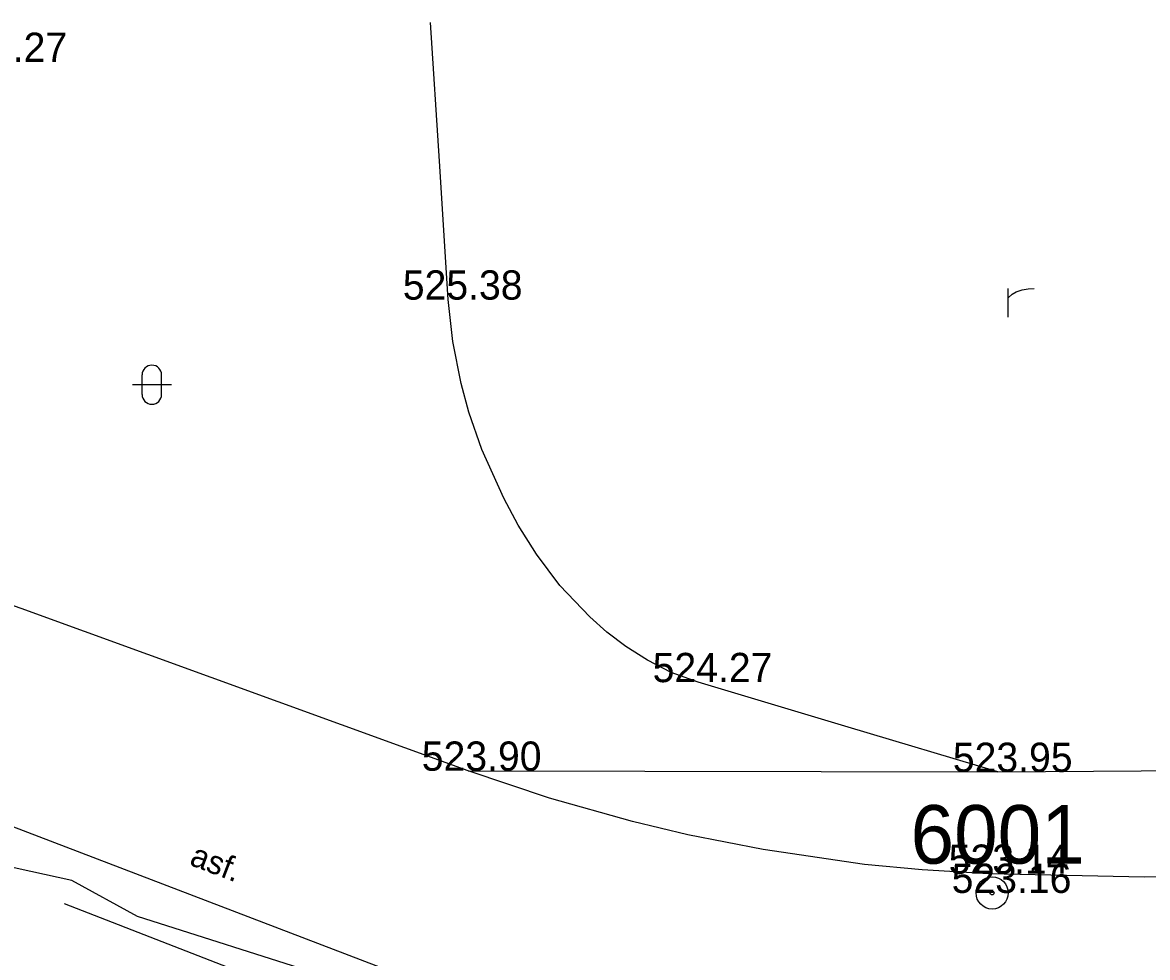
# Model space of a CAD drawing. Extents: x -669393 to -668650, y -1126925 to -1126294.
# Drawn here: x -668886.74 to -668857.93, y -1126829.82 to -1126805.87 of the extents above; entities that cross this region are included whole.
import ezdxf

# ---------------------------------------------------------------- set-up
doc = ezdxf.new("R2010")
doc.units = 0
for name, color, linetype in [('G_Bod_tecka', 7, 'Continuous'), ('G_Bod_vyska', 7, 'Continuous'), ('G_Bodove_pole', 7, 'Continuous'), ('G_Breh_Teren', 7, 'Continuous'), ('G_Plochy_zpevnene', 7, 'Continuous'), ('G_Popisy_povrchu', 7, 'Continuous'), ('G_Z_KANAL_podz_priblizne', 7, 'Continuous'), ('G_Z_SPOJE_podz_kotovane', 7, 'Continuous'), ('G_Zelen-rozhrani', 7, 'Continuous'), ('G_Zelen-Znacky', 7, 'Continuous'), ('Vrstva 18', 7, 'Continuous')]:
    doc.layers.add(name, color=color, linetype=linetype)

msp = doc.modelspace()

# ---------------------------------------------------------------- linework, layer by layer
at = {"layer": 'G_Bod_tecka'}
for p, q in [((-668875.84, -1126812.97), (-668875.84, -1126812.97)), ((-668869.44, -1126822.77), (-668869.44, -1126822.77)), ((-668875.33, -1126825.04), (-668875.33, -1126825.04)), ((-668861.76, -1126825.07), (-668861.76, -1126825.07)), ((-668862, -1126827.68), (-668862, -1126827.68)), ((-668861.91, -1126828.17), (-668861.91, -1126828.17))]:
    msp.add_line(p, q, dxfattribs=at)
at = {"layer": 'G_Bodove_pole'}
for radius in [0.412, 0.05]:
    msp.add_circle((-668861.91, -1126828.17), radius, dxfattribs=at)
at = {"layer": 'G_Breh_Teren'}
msp.add_line((-668875.33, -1126825.04), (-668861.76, -1126825.07), dxfattribs=at)
msp.add_lwpolyline([(-668861.76, -1126825.07), (-668854.42, -1126825.02), (-668847.08, -1126824.98), (-668829.4, -1126824.94), (-668820.56, -1126824.84), (-668816.14, -1126824.73), (-668811.72, -1126824.57), (-668793.98, -1126823.82), (-668776.23, -1126823.06)], dxfattribs=at)
at = {"layer": 'G_Plochy_zpevnene'}
for points in [[(-668794.8, -1126825.6), (-668795.84, -1126825.39), (-668796.83, -1126825.24), (-668798.69, -1126825.06), (-668800.34, -1126825.01), (-668801.78, -1126825.02), (-668811.94, -1126825.73), (-668821.93, -1126826.15), (-668831.92, -1126826.62), (-668839.86, -1126827.06), (-668847.81, -1126827.52), (-668851.35, -1126827.68), (-668854.02, -1126827.75), (-668858.01, -1126827.77), (-668862, -1126827.68), (-668863.7, -1126827.58), (-668865.18, -1126827.44), (-668867.77, -1126827.06), (-668869.7, -1126826.68), (-668871.12, -1126826.34), (-668873.25, -1126825.74), (-668875.33, -1126825.04), (-668886.78, -1126820.88), (-668897.18, -1126817.23)], [(-668898.95, -1126821.9), (-668887.43, -1126826.31), (-668875.91, -1126830.71), (-668875.01, -1126831.01), (-668874.15, -1126831.24), (-668872.51, -1126831.53), (-668871.04, -1126831.69), (-668865.85, -1126831.96), (-668864.56, -1126832.08), (-668863.6, -1126832.21), (-668862.2, -1126832.5), (-668860.82, -1126832.92), (-668858.11, -1126834.02), (-668855.45, -1126835.23), (-668851.15, -1126837.23), (-668849.02, -1126838.26), (-668846.94, -1126839.39), (-668832.81, -1126847.59), (-668818.68, -1126855.79)]]:
    msp.add_lwpolyline(points, dxfattribs=at)
at = {"layer": 'G_Z_KANAL_podz_priblizne'}
msp.add_lwpolyline([(-668885.68, -1126828.44), (-668837.62, -1126847.14), (-668813.42, -1126866.74)], dxfattribs=at)
at = {"layer": 'G_Z_SPOJE_podz_kotovane'}
msp.add_lwpolyline([(-668874.36, -1126831.78), (-668883.8, -1126828.77), (-668885.48, -1126827.85), (-668888.02, -1126827.3), (-668901.12, -1126822.58), (-668907.14, -1126819.42), (-668924.36, -1126812.03), (-668938.42, -1126806.85)], dxfattribs=at)
at = {"layer": 'G_Zelen-rozhrani'}
msp.add_lwpolyline([(-668861.76, -1126825.07), (-668865.6, -1126823.92), (-668869.44, -1126822.77), (-668870.13, -1126822.52), (-668870.74, -1126822.21), (-668871.29, -1126821.86), (-668871.78, -1126821.49), (-668872.21, -1126821.1), (-668872.98, -1126820.29), (-668873.58, -1126819.49), (-668874.05, -1126818.75), (-668874.42, -1126818.06), (-668874.98, -1126816.81), (-668875.31, -1126815.85), (-668875.51, -1126815.12), (-668875.72, -1126814.04), (-668875.84, -1126812.97), (-668876.06, -1126809.42), (-668876.29, -1126805.87)], dxfattribs=at)
at = {"layer": 'G_Zelen-Znacky'}
for p, q in [((-668861.5, -1126813.421), (-668861.5, -1126812.689)), ((-668883.68, -1126815.4), (-668883.68, -1126814.9)), ((-668883.18, -1126815.4), (-668883.18, -1126814.9)), ((-668882.93, -1126815.15), (-668883.93, -1126815.15))]:
    msp.add_line(p, q, dxfattribs=at)
msp.add_lwpolyline([(-668861.5, -1126812.925), (-668861.398, -1126812.83), (-668861.295, -1126812.767), (-668861.138, -1126812.72), (-668860.988, -1126812.697), (-668860.831, -1126812.689)], dxfattribs=at)
for centre, start, end in [((-668883.43, -1126814.9), 0, 180), ((-668883.43, -1126815.4), 180, 0)]:
    msp.add_arc(centre, 0.25, start, end, dxfattribs=at)
at = {"layer": 'Vrstva 18'}
msp.add_lwpolyline([(-668885.68, -1126828.44), (-668837.62, -1126847.14), (-668813.42, -1126866.74)], dxfattribs=at)
msp.add_lwpolyline([(-668885.68, -1126828.44), (-668837.62, -1126847.14), (-668813.42, -1126866.74)], dxfattribs=at)

# ---------------------------------------------------------------- texts
at = {"layer": 'G_Bod_vyska'}
for s, p in [('526.27', (-668888.668, -1126806.88)), ('525.38', (-668877.004, -1126812.97)), ('524.27', (-668870.604, -1126822.77)), ('523.90', (-668876.518, -1126825.04)), ('523.95', (-668862.916, -1126825.07)), ('523.14', (-668863.022, -1126827.68)), ('523.16', (-668862.946, -1126828.17))]:
    msp.add_text(s, height=0.75, dxfattribs=at).set_placement(p)
at = {"layer": 'G_Bodove_pole'}
msp.add_text('6001', height=1.5, dxfattribs=at).set_placement((-668863.999, -1126827.42))
at = {"layer": 'G_Popisy_povrchu'}
msp.add_text('asf.', height=0.6, rotation=339.0796, dxfattribs=at).set_placement((-668882.494, -1126827.441))

doc.saveas('drawing.dxf')
